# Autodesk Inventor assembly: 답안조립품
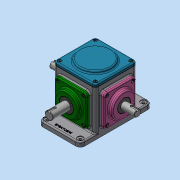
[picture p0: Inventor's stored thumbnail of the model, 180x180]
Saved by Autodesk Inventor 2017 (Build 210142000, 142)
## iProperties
Part Number: 답안조립품
Material: 일반
Document SubType Name: Assembly
Designer: MRC
Author: MRC
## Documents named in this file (16)
- C:\Users\MRC\Desktop\620307V1012\답안조립품.iam
- C:\Users\MRC\Desktop\620307V1012\본체.ipt
- C:\Users\MRC\Desktop\620307V1012\개스킷.ipt
- C:\Users\MRC\Desktop\620307V1012\메인베벨기어.ipt
- C:\Users\MRC\Desktop\620307V1012\메인축.ipt
- C:\Users\MRC\Desktop\620307V1012\메인커버.ipt
- C:\Users\MRC\Desktop\620307V1012\베어링 6203.ipt
- C:\Users\MRC\Desktop\620307V1012\베어링 6204.ipt
- C:\Users\MRC\Desktop\620307V1012\볼트 M4.ipt
- C:\Users\MRC\Desktop\620307V1012\상부커버.ipt
- C:\Users\MRC\Desktop\620307V1012\서브베벨기어.ipt
- C:\Users\MRC\Desktop\620307V1012\서브축.ipt
- C:\Users\MRC\Desktop\620307V1012\서브커버.ipt
- C:\Users\MRC\Desktop\620307V1012\오일 실 17 32 8.ipt
- C:\Users\MRC\Desktop\620307V1012\오일 실 20 35 8.ipt
- C:\Users\MRC\Desktop\620307V1012\키 4x4.ipt
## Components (1 placed, 1 different names)
1. 개스킷:1
